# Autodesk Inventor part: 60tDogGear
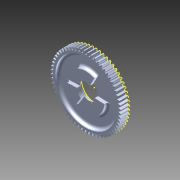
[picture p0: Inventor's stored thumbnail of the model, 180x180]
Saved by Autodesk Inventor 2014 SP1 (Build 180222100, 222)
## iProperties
Created: 2014-11
Part Number: 60tDogGear
Material: Generic
Document SubType Name: Modeling
Designer: Michael
Density: 1 g/cm^3
Appearance: Default
Title: 217-3420-STEP.STEP
Description: STEP AP214
Creation Date: 2013-12-09
Sending System: SolidWorks 2013
Preprocessor: SwSTEP 2.0
Author: Michael
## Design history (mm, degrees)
node "60tDogGear1"
sketch "Sketch1"
  geometry: C1 r 14.288 at (35.017, 14.587) reference; A1 r 39.37 centre (35.017, 14.587) between (-2.259, 1.918) and (-1.87, 0.826) reference; A2 r 39.37 centre (35.017, 14.587) between (-0.731, -1.909) and (-0.229, -2.955) reference; A3 r 39.37 centre (35.017, 14.587) between (1.19, -5.555) and (1.798, -6.543) reference; A4 r 39.37 centre (35.017, 14.587) between (3.48, -8.981) and (4.188, -9.899) reference; A5 r 39.37 centre (35.017, 14.587) between (6.117, -12.148) and (6.917, -12.988) reference; A6 r 39.37 centre (35.017, 14.587) between (9.07, -15.022) and (9.953, -15.774) reference; A7 r 39.37 centre (35.017, 14.587) between (12.307, -17.572) and (13.264, -18.227) reference; A8 r 39.37 centre (35.017, 14.587) between (15.793, -19.77) and (16.813, -20.321) reference; A9 r 39.37 centre (35.017, 14.587) between (19.489, -21.591) and (20.562, -22.033) reference; A10 r 39.37 centre (35.017, 14.587) between (23.356, -23.016) and (24.469, -23.343) reference; A11 r 39.37 centre (35.017, 14.587) between (27.351, -24.029) and (28.492, -24.238) reference; A12 r 39.37 centre (35.017, 14.587) between (31.429, -24.619) and (32.586, -24.708) reference; A13 r 39.37 centre (35.017, 14.587) between (35.547, -24.779) and (36.706, -24.746) reference; A14 r 39.37 centre (35.017, 14.587) between (39.659, -24.508) and (40.809, -24.354) reference; A15 r 39.37 centre (35.017, 14.587) between (43.72, -23.809) and (44.847, -23.536) reference; A16 r 39.37 centre (35.017, 14.587) between (47.686, -22.689) and (48.778, -22.299) reference; A17 r 39.37 centre (35.017, 14.587) between (51.513, -21.16) and (52.559, -20.659) reference; A18 r 39.37 centre (35.017, 14.587) between (55.159, -19.24) and (56.147, -18.632) reference; A19 r 39.37 centre (35.017, 14.587) between (58.585, -16.949) and (59.503, -16.241) reference; A20 r 39.37 centre (35.017, 14.587) between (61.752, -14.313) and (62.592, -13.513) reference; A21 r 39.37 centre (35.017, 14.587) between (64.627, -11.36) and (65.378, -10.476) reference; A22 r 39.37 centre (35.017, 14.587) between (67.177, -8.123) and (67.832, -7.166) reference; A23 r 39.37 centre (35.017, 14.587) between (69.374, -4.637) and (69.926, -3.616) reference; A24 r 39.37 centre (35.017, 14.587) between (71.195, -0.94) and (71.637, 0.132) reference; A25 r 39.37 centre (35.017, 14.587) between (72.62, 2.927) and (72.947, 4.039) reference; A26 r 39.37 centre (35.017, 14.587) between (73.633, 6.921) and (73.842, 8.062) reference; A27 r 39.37 centre (35.017, 14.587) between (74.223, 11) and (74.312, 12.156) reference; A28 r 39.37 centre (35.017, 14.587) between (74.383, 15.118) and (74.35, 16.277) reference; A29 r 39.37 centre (35.017, 14.587) between (74.112, 19.23) and (73.958, 20.379) reference; A30 r 39.37 centre (35.017, 14.587) between (73.413, 23.291) and (73.14, 24.418) reference; A31 r 39.37 centre (35.017, 14.587) between (72.293, 27.257) and (71.903, 28.349) reference; A32 r 39.37 centre (35.017, 14.587) between (70.764, 31.084) and (70.263, 32.129) reference; A33 r 39.37 centre (35.017, 14.587) between (68.844, 34.73) and (68.236, 35.717) reference; A34 r 39.37 centre (35.017, 14.587) between (66.553, 38.155) and (65.845, 39.074) reference; A35 r 39.37 centre (35.017, 14.587) between (63.917, 41.323) and (63.117, 42.162) reference; A36 r 39.37 centre (35.017, 14.587) between (60.964, 44.197) and (60.081, 44.949) reference; A37 r 39.37 centre (35.017, 14.587) between (57.727, 46.747) and (56.77, 47.402) reference; A38 r 39.37 centre (35.017, 14.587) between (54.241, 48.945) and (53.22, 49.496) reference; A39 r 39.37 centre (35.017, 14.587) between (50.544, 50.766) and (49.472, 51.208) reference; A40 r 39.37 centre (35.017, 14.587) between (46.677, 52.191) and (45.565, 52.518) reference; A41 r 39.37 centre (35.017, 14.587) between (42.683, 53.204) and (41.542, 53.413) reference; A42 r 39.37 centre (35.017, 14.587) between (38.604, 53.794) and (37.448, 53.882) reference; A43 r 39.37 centre (35.017, 14.587) between (34.486, 53.954) and (33.327, 53.921) reference; A44 r 39.37 centre (35.017, 14.587) between (30.374, 53.683) and (29.225, 53.529) reference; A45 r 39.37 centre (35.017, 14.587) between (26.313, 52.983) and (25.186, 52.71) reference; A46 r 39.37 centre (35.017, 14.587) between (22.348, 51.863) and (21.255, 51.474) reference; A47 r 39.37 centre (35.017, 14.587) between (18.521, 50.335) and (17.475, 49.833) reference; A48 r 39.37 centre (35.017, 14.587) between (14.874, 48.415) and (13.887, 47.807) reference; A49 r 39.37 centre (35.017, 14.587) between (11.449, 46.124) and (10.53, 45.416) reference; A50 r 39.37 centre (35.017, 14.587) between (8.281, 43.487) and (7.442, 42.687) reference; A51 r 39.37 centre (35.017, 14.587) between (5.407, 40.535) and (4.656, 39.651) reference; A52 r 39.37 centre (35.017, 14.587) between (2.857, 37.297) and (2.202, 36.34) reference; A53 r 39.37 centre (35.017, 14.587) between (0.659, 33.811) and (0.108, 32.791) reference; A54 r 39.37 centre (35.017, 14.587) between (-1.162, 30.115) and (-1.604, 29.042) reference; A55 r 39.37 centre (35.017, 14.587) between (-2.587, 26.248) and (-2.914, 25.135) reference; A56 r 39.37 centre (35.017, 14.587) between (-3.6, 22.253) and (-3.809, 21.113) reference; A57 r 39.37 centre (35.017, 14.587) between (-4.189, 18.175) and (-4.278, 17.018) reference; A58 r 39.37 centre (35.017, 14.587) between (-4.35, 14.057) and (-4.317, 12.898) reference; A59 r 39.37 centre (35.017, 14.587) between (-4.079, 9.945) and (-3.925, 8.795) reference; A60 r 39.37 centre (35.017, 14.587) between (-3.379, 5.884) and (-3.106, 4.757) reference; A61 r 0.558 centre (35.656, 51.658) between (35.098, 51.672) and (35.72, 51.104); A62 r 0.532 centre (32.307, 51.544) between (32.359, 51.014) and (32.839, 51.551)
  constraints: 4 point on circle, 2 centre point, 65 other
node "BackBore"
node "Base1"
